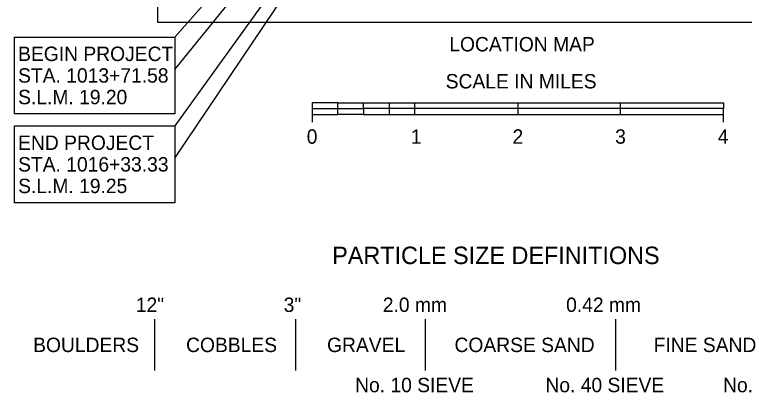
# Model space of a CAD drawing. Extents: x -21.7 to 34, y 0 to 22.
# Drawn here: x 22.03 to 29.12, y 10.41 to 14.08 of the extents above; entities that cross this region are included whole.
import ezdxf

# ---------------------------------------------------------------- set-up
doc = ezdxf.new("R2010")
doc.units = 0
doc.layers.add('SH_Data', color=7, linetype='Continuous')
doc.layers.add('SH_Text', color=7, linetype='Continuous')

msp = doc.modelspace()

# ---------------------------------------------------------------- linework, layer by layer
at = {"layer": 'SH_Data'}
for p, q in [((25.1667, 13.22), (24.9167, 13.22)), ((24.9167, 13.22), (24.9167, 13.1638)), ((25.1667, 13.22), (25.4167, 13.22)), ((25.1667, 13.1638), (25.1667, 13.22)), ((25.4167, 13.1638), (25.4167, 13.22)), ((25.4167, 13.22), (25.6667, 13.22)), ((25.6667, 13.22), (25.9167, 13.22)), ((25.6667, 13.22), (25.6667, 13.1638)), ((25.9167, 13.1638), (25.9167, 13.22)), ((25.9167, 13.22), (26.9167, 13.22)), ((26.9167, 13.22), (26.9167, 13.1638)), ((26.9167, 13.22), (27.9167, 13.22)), ((27.9167, 13.1638), (27.9167, 13.22)), ((27.9167, 13.22), (28.9167, 13.22)), ((28.9167, 13.22), (28.9167, 13.1638)), ((24.9167, 13.1638), (24.9167, 13.0325)), ((24.9167, 13.1638), (25.1667, 13.1638)), ((25.1667, 13.1638), (25.4167, 13.1638)), ((25.1667, 13.1075), (25.1667, 13.1638)), ((25.4167, 13.1638), (25.4167, 13.1075)), ((25.6667, 13.1638), (25.4167, 13.1638)), ((25.9167, 13.1638), (25.6667, 13.1638)), ((25.6667, 13.1638), (25.6667, 13.1075)), ((25.9167, 13.1075), (25.9167, 13.1638)), ((26.9167, 13.1638), (25.9167, 13.1638)), ((27.9167, 13.1638), (26.9167, 13.1638)), ((26.9167, 13.1638), (26.9167, 13.1075)), ((27.9167, 13.1075), (27.9167, 13.1638)), ((28.9167, 13.1638), (27.9167, 13.1638)), ((28.9167, 13.0325), (28.9167, 13.1638)), ((24.9167, 13.1075), (25.1667, 13.1075)), ((25.4167, 13.1075), (25.1667, 13.1075)), ((25.4167, 13.1075), (25.6667, 13.1075)), ((25.6667, 13.1075), (25.9167, 13.1075)), ((25.9167, 13.1075), (26.9167, 13.1075)), ((26.9167, 13.1075), (27.9167, 13.1075)), ((27.9167, 13.1075), (28.9167, 13.1075)), ((23.3896, 10.6173), (23.3896, 11.1173)), ((24.7596, 10.6173), (24.7596, 11.1173)), ((26.0196, 10.6173), (26.0196, 11.1173)), ((27.8696, 10.6173), (27.8696, 11.1173))]:
    msp.add_line(p, q, dxfattribs=at)
msp.add_lwpolyline([(23.4167, 21), (30.4167, 21), (30.4167, 14), (23.4167, 14)], close=True, dxfattribs=at)
at = {"layer": 'SH_Text'}
for points in [[(23.5845, 13.5445), (26.7756, 17.4787), (23.5845, 13.8593)], [(23.5845, 12.6836), (26.8092, 17.4787), (23.5845, 12.9954)], [(22.0251, 13.8593), (23.5845, 13.8593), (23.5845, 13.1131), (22.0251, 13.1131)], [(22.0251, 12.9954), (23.5845, 12.9954), (23.5845, 12.2493), (22.0251, 12.2493)]]:
    msp.add_lwpolyline(points, close=True, dxfattribs=at)

# ---------------------------------------------------------------- texts
for s, height, p in [('LOCATION MAP', 0.14, (26.2513, 13.72)), ('BEGIN PROJECT', 0.14, (22.0593, 13.6264)), ('STA. 1013+71.58', 0.14, (22.0593, 13.4164)), ('SCALE IN MILES', 0.14, (26.216, 13.36)), ('S.L.M. 19.20', 0.14, (22.0593, 13.2064)), ('0', 0.14, (24.8651, 12.8225)), ('1', 0.14, (25.8782, 12.8225)), ('2', 0.14, (26.866, 12.8225)), ('3', 0.14, (27.8639, 12.8225)), ('4', 0.14, (28.8615, 12.8225)), ('END PROJECT', 0.14, (22.0593, 12.7625)), ('STA. 1016+33.33', 0.14, (22.0593, 12.5525)), ('S.L.M. 19.25', 0.14, (22.0593, 12.3425)), ('PARTICLE SIZE DEFINITIONS', 0.17, (25.113, 11.6525)), ('12"', 0.14, (23.2034, 11.1873)), ('3"', 0.14, (24.6411, 11.1873)), ('2.0 mm', 0.14, (25.6049, 11.1873)), ('0.42 mm', 0.14, (27.3872, 11.1873)), ('BOULDERS', 0.14, (22.2054, 10.7973)), ('COBBLES', 0.14, (23.6923, 10.7973)), ('GRAVEL', 0.14, (25.0628, 10.7973)), ('COARSE SAND', 0.14, (26.3019, 10.7973)), ('FINE SAND', 0.14, (28.238, 10.7973)), ('No. 10 SIEVE', 0.14, (25.3358, 10.4073)), ('No. 40 SIEVE', 0.14, (27.1858, 10.4073)), ('No. 200 SIEVE', 0.14, (28.9131, 10.4073))]:
    msp.add_text(s, height=height, dxfattribs=at).set_placement(p)

doc.saveas('drawing.dxf')
